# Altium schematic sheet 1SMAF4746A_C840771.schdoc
size 127 x 101 mm
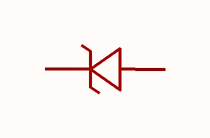
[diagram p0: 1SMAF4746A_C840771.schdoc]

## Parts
D?  1smaf4746a  [SMAF_L3.5-W2.6-LS4.7-RD]  (value not drawn)

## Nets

Not connected (* = marked no-connect by the designer): D? 1(C) 2(A)

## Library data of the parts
D? = 1smaf4746a: 二极管配置:1个独立式;稳压值(标称值):18V;稳压值(范围):16.8V~19.2V;耗散功率(Pd):1W;; Manufacturer: MDD(辰达半导体); Symbol: 1SMAF4746A_C840771; AddInBom: yes; ModelId: 4caf566195a049cf809ac17c4d641932; ModelName: SMAF_L3.5-W2.6-LS4.7-RD-1; ModelTransform: 183.0705,102.362,0,0,0,0,0,0,0; Diode Configuration: 1个独立式; Zener Voltage(Nom): 18V; Reverse Leakage Current (Ir): 5uA; Pd - Power Dissipation: 1W; Impedance(Zzt): 20Ω; Operating Junction Temperature Range: -55℃~+150℃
